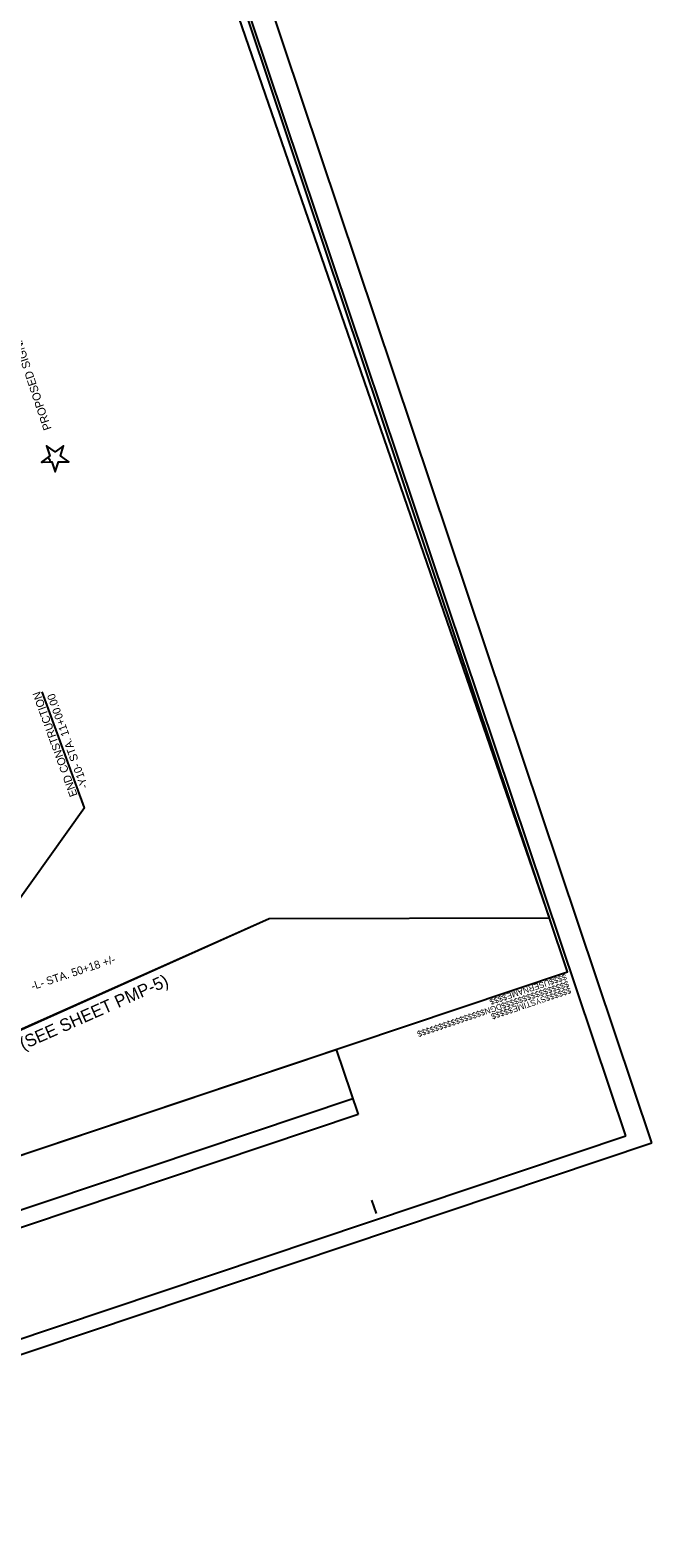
# Model space of a CAD drawing. Extents: x 1615436 to 1617119, y 903110 to 905145.
# Drawn here: x 1616462 to 1617010, y 903110 to 904439 of the extents above; entities that cross this region are included whole.
import ezdxf

# ---------------------------------------------------------------- set-up
doc = ezdxf.new("R2010")
doc.units = 0
for name, color, linetype in [('Default', 7, 'Continuous'), ('Matchline', 7, 'Continuous'), ('Matchline Text', 7, 'Continuous'), ('Prop Horizontal Alignment Curve and Spiral Data', 7, 'Continuous'), ('Prop Horizontal Alignment Station Label', 7, 'Continuous'), ('Sheet Block Revision CELL', 7, 'Continuous'), ('Sheet Layout Plan Border', 7, 'Continuous'), ('Sheet Plan CELL', 7, 'Continuous'), ('Sheet Plot Border Inside CELL', 7, 'Continuous'), ('Sheet Plot Border Outside CELL', 7, 'Continuous'), ('Text', 7, 'Continuous')]:
    doc.layers.add(name, color=color, linetype=linetype)

msp = doc.modelspace()

# ---------------------------------------------------------------- linework, layer by layer
at = {"layer": 'Default'}
for p, q in [((1616477.9, 904063), (1616472.6, 904059.1)), ((1616472.6, 904059.1), (1616472.8, 904058.6)), ((1616472.8, 904058.6), (1616472.6, 904059.1)), ((1616472.8, 904058.6), (1616479.6, 904058.7))]:
    msp.add_line(p, q, dxfattribs=at)
for points in [[(1616479.4, 904064.1), (1616472, 904058.6), (1616481.2, 904058.7), (1616484.1, 904050), (1616486.9, 904058.8), (1616496.1, 904058.8), (1616488.6, 904064.2), (1616491.3, 904072.9), (1616484, 904067.5), (1616476.5, 904072.8), (1616479.4, 904064.1)], [(1616479.6, 904058.7), (1616481.2, 904058.7), (1616484.1, 904050), (1616486.9, 904058.8), (1616496.1, 904058.8), (1616488.6, 904064.2), (1616491.3, 904072.9), (1616484, 904067.5), (1616476.5, 904072.8), (1616479.4, 904064.1), (1616477.9, 904063)], [(1616472.6, 904059.1), (1616472, 904058.6), (1616472.8, 904058.6)]]:
    msp.add_lwpolyline(points, dxfattribs=at)
msp.add_ellipse((1616472.8, 904058.3), major_axis=(-0.95, 6.77), ratio=0.999591, start_param=4.623228, end_param=5.312334, dxfattribs=at)
msp.add_ellipse((1616472.8, 904058.3), major_axis=(-0.95, 6.77), ratio=0.999591, start_param=4.623228, end_param=5.312334, dxfattribs=at)
at = {"layer": 'Matchline'}
msp.add_line((1616172.6, 903432.8), (1616672.6, 903656.2), dxfattribs=at)
at = {"layer": 'Prop Horizontal Alignment Curve and Spiral Data'}
msp.add_line((1616509.8, 903753.8), (1616426.4, 903636.9), dxfattribs=at)
at = {"layer": 'Prop Horizontal Alignment Station Label'}
msp.add_line((1616509.8, 903753.8), (1616472.7, 903856.2), dxfattribs=at)
at = {"layer": 'Sheet Block Revision CELL'}
msp.add_line((1616746.5, 903497.4), (1615996.9, 903246), dxfattribs=at)
msp.add_lwpolyline([(1616751.1, 903483.7), (1616001.5, 903232.2), (1615982.2, 903289.6), (1616731.8, 903541)], close=True, dxfattribs=at)
at = {"layer": 'Sheet Layout Plan Border'}
msp.add_lwpolyline([(1616672.6, 903656.2), (1616919.8, 903656.8), (1616590.6, 904611.2), (1616386.8, 904624.4), (1616334.8, 904821.6), (1616466, 905009.6), (1615641.1, 904732.9), (1615700, 904557.2), (1615560.3, 904510.3), (1615954.2, 903336.2)], close=True, dxfattribs=at)
at = {"layer": 'Sheet Plan CELL'}
for p, q in [((1616935.7, 903609.4), (1616935.7, 903609.4)), ((1616767.2, 903396.3), (1616763.2, 903408.1))]:
    msp.add_line(p, q, dxfattribs=at)
msp.add_lwpolyline([(1615463.1, 904697.6), (1615940.2, 903275.5), (1616935.7, 903609.4), (1616458.6, 905031.5)], close=True, dxfattribs=at)
at = {"layer": 'Sheet Plot Border Inside CELL'}
msp.add_lwpolyline([(1616986.9, 903464.7), (1616457, 905044.2), (1615456.8, 904708.7), (1615986.6, 903129.2)], close=True, dxfattribs=at)
at = {"layer": 'Sheet Plot Border Outside CELL'}
msp.add_lwpolyline([(1617010, 903458.7), (1616474.6, 905054.8), (1615436.4, 904706.6), (1615971.8, 903110.5)], close=True, dxfattribs=at)

# ---------------------------------------------------------------- texts
at = {"layer": 'Default'}
msp.add_text('PROPOSED SIGNALIZED INTERSECTION', height=7.199, rotation=108.5432, dxfattribs=at).set_placement((1616480.9, 904088))
at = {"layer": 'Matchline Text'}
msp.add_text('MATCHLINE -L- STA. 50+00.00 (SEE SHEET PMP-5)', height=11, rotation=23.8606, dxfattribs=at).set_placement((1616260.2, 903453.8))
at = {"layer": 'Prop Horizontal Alignment Station Label'}
for s, p in [('END CONSTRUCTION', (1616503.8, 903765.1)), ('-Y10- STA. 11+00.00', (1616513.3, 903772.3))]:
    msp.add_text(s, height=7, rotation=109.9333, dxfattribs=at).set_placement(p)
at = {"layer": 'Sheet Plan CELL'}
for s, p in [('$$$$USERNAME$$$$', (1616933.8, 903607.6)), ('$$$$$$$$$$$$$$$$DGN$$$$$$$$$$$$$$$$', (1616935.9, 903601.4)), ('$$$$$$SYSTIME$$$$$', (1616937.8, 903595.7))]:
    msp.add_text(s, height=5.25, rotation=198.5432, dxfattribs=at).set_placement(p)
at = {"layer": 'Text'}
msp.add_text('-L- STA. 50+18 +/-', height=7, rotation=18.3607, dxfattribs=at).set_placement((1616464.1, 903593.1))

doc.saveas('drawing.dxf')
